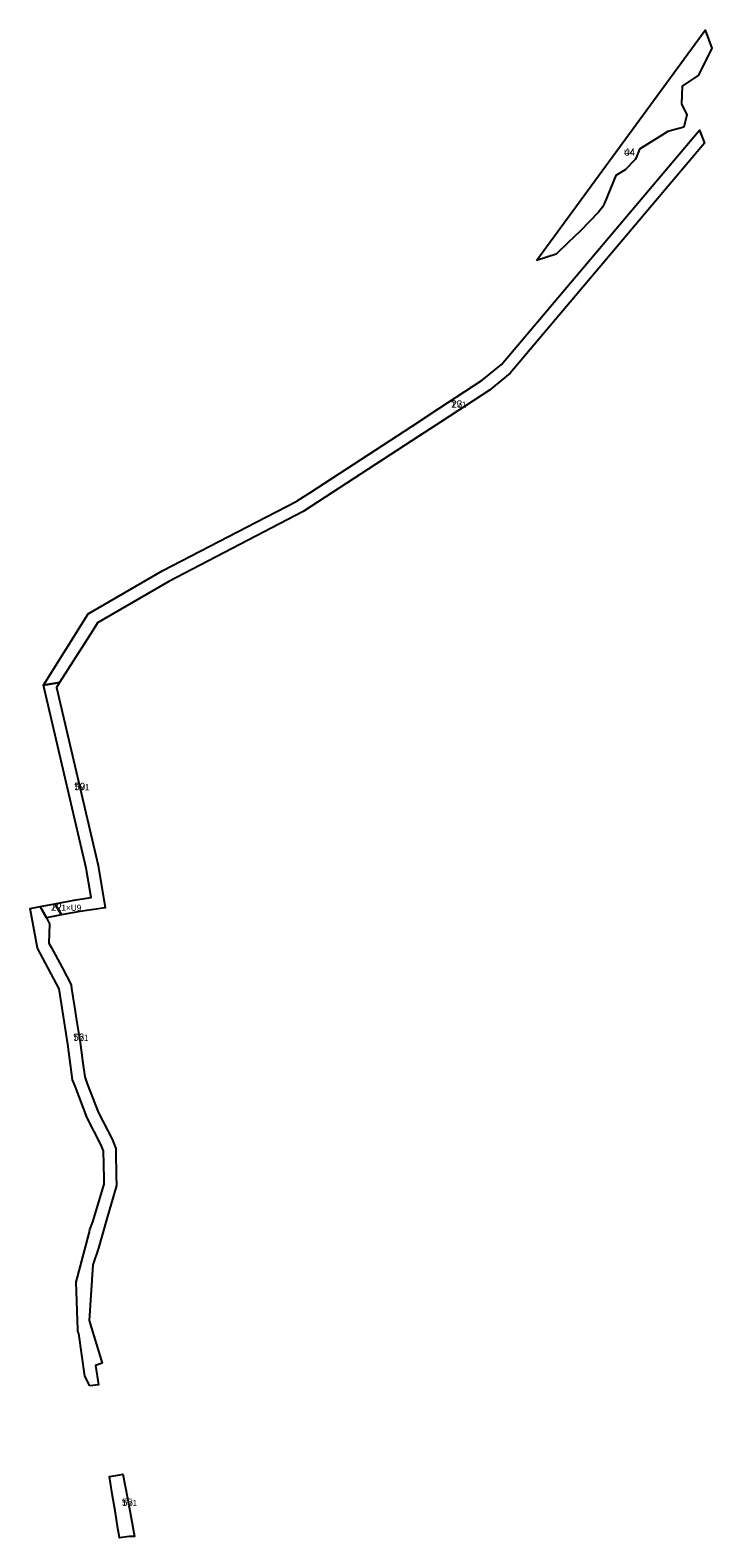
# Model space of a CAD drawing. Extents: x -521229 to -518220, y -1182332 to -1179899.
# Drawn here: x -519555 to -519000, y -1181125 to -1179899 of the extents above; entities that cross this region are included whole.
import ezdxf

# ---------------------------------------------------------------- set-up
doc = ezdxf.new("R2010")
doc.units = 0
for name, color, linetype in [('96120023', 7, 'Continuous'), ('96140023', 7, 'Continuous'), ('ID_VPO', 7, 'Continuous'), ('ID_VPS', 7, 'Continuous')]:
    doc.layers.add(name, color=color, linetype=linetype)

msp = doc.modelspace()

# ---------------------------------------------------------------- linework, layer by layer
at = {"layer": '96120023'}
for points in [[(-519543.8, -1180432.1), (-519507.4, -1180374), (-519446.6, -1180338.8), (-519370.8, -1180299.4), (-519337.8, -1180282.3), (-519337.7, -1180282.2), (-519337.5, -1180282.1), (-519327.1, -1180275.5), (-519244, -1180221.2), (-519222.2, -1180207), (-519187, -1180183.9), (-519171.3, -1180171.2), (-519012, -1179982.6), (-519010.3, -1179980.5), (-519006.1, -1179991.2), (-519164.2, -1180178.3), (-519181.1, -1180192), (-519220, -1180217.4), (-519238.6, -1180229.5), (-519332.5, -1180290.7), (-519441.8, -1180347.6), (-519499.7, -1180381.2), (-519503.7, -1180387.4), (-519530.6, -1180429.8)], [(-519543.8, -1180432.1), (-519530.6, -1180429.8), (-519533.1, -1180433.9), (-519499.2, -1180578.7), (-519493.5, -1180613), (-519515.7, -1180616.4), (-519529, -1180618.9), (-519534.4, -1180609.7), (-519517.4, -1180606.5), (-519505, -1180604.6), (-519509, -1180580.7)], [(-519505.9, -1181001.9), (-519510.2, -1180994.1), (-519515.1, -1180959.2), (-519515.9, -1180957.6), (-519515.9, -1180956.3), (-519517.2, -1180917.4), (-519506.7, -1180877.7), (-519505.9, -1180874.8), (-519503.5, -1180868.4), (-519494.4, -1180837.7), (-519494.5, -1180833.2), (-519495, -1180810.8), (-519497.1, -1180805.5), (-519508.2, -1180783.9), (-519518, -1180758.1), (-519520, -1180752.9), (-519523.9, -1180724), (-519530.9, -1180678.9), (-519548.5, -1180645.8), (-519554.6, -1180613.6), (-519546.3, -1180612), (-519541.3, -1180621.3), (-519538.7, -1180626), (-519539.3, -1180641.8), (-519537.6, -1180645), (-519528.5, -1180661.7), (-519521.3, -1180675.7), (-519520.9, -1180678.7), (-519518.6, -1180693.9), (-519516.6, -1180706.2), (-519514, -1180722.6), (-519511.6, -1180739.4), (-519510.2, -1180750.4), (-519508.1, -1180756.2), (-519499, -1180779.8), (-519488, -1180801.3), (-519485, -1180808.7), (-519485, -1180811.4), (-519484.6, -1180831.1), (-519484.4, -1180839), (-519492.5, -1180866.9), (-519498.9, -1180889.8), (-519503.7, -1180903.5), (-519506.5, -1180948.8), (-519495.9, -1180983.5), (-519495.9, -1180983.5), (-519501.3, -1180985.2), (-519499.1, -1181001), (-519505.9, -1181001.9)], [(-519534.4, -1180609.7), (-519529, -1180618.9), (-519541.3, -1180621.3), (-519546.3, -1180612)], [(-519483.4, -1181074.6), (-519482.9, -1181074.5), (-519481.7, -1181074.3), (-519479.1, -1181073.8), (-519475.5, -1181093.3), (-519472.8, -1181107.8), (-519469.7, -1181124.3), (-519472.4, -1181124.3), (-519474.1, -1181124.5), (-519482, -1181125.5), (-519482.2, -1181123.5), (-519483.2, -1181117.8), (-519485.2, -1181105.1), (-519488, -1181089.8), (-519489.3, -1181080.9), (-519490.1, -1181075.7), (-519486.8, -1181075.1), (-519485, -1181074.8)]]:
    msp.add_lwpolyline(points, close=True, dxfattribs=at)
at = {"layer": '96140023'}
for points in [[(-519142.9, -1180086.6), (-519005.7, -1179899.2), (-519000.3, -1179913.9), (-519011.1, -1179935.9), (-519024.4, -1179944.7), (-519024.9, -1179959.2), (-519020.6, -1179968), (-519023, -1179978), (-519036, -1179981.6), (-519059.1, -1179995.9), (-519061.8, -1180003.2), (-519062.7, -1180004.4), (-519070.6, -1180012.7), (-519078.4, -1180017.4), (-519087.6, -1180040), (-519089.2, -1180043.2), (-519092.5, -1180047.2), (-519107.3, -1180062.6), (-519117, -1180071.9), (-519126.8, -1180081.3)], [(-519534.4, -1180609.7), (-519529, -1180618.9), (-519541.3, -1180621.3), (-519546.3, -1180612), (-519546.3, -1180612)]]:
    msp.add_lwpolyline(points, close=True, dxfattribs=at)

# ---------------------------------------------------------------- texts
at = {"layer": '96120023'}
for s, rotation, p in [('TV1', 0, (-519212.1, -1180206.3)), ('TV1', 0, (-519518.7, -1180517.4)), ('TV1×U9', 360, (-519537.7, -1180615.5)), ('TV1', 0, (-519519.5, -1180721.3)), ('TV1', 360, (-519479.9, -1181099.6))]:
    msp.add_text(s, height=5, rotation=rotation, dxfattribs=at).set_placement(p)
at = {"layer": '96140023'}
for s, p in [('U4', (-519071.6, -1180001.3)), ('TV1×U9', (-519537.7, -1180615.5))]:
    msp.add_text(s, height=5, rotation=360, dxfattribs=at).set_placement(p)
at = {"layer": 'ID_VPO'}
for s, p in [('44', (-519071.6, -1180001.3)), ('22', (-519537.7, -1180615.5))]:
    msp.add_text(s, height=6, rotation=360, dxfattribs=at).set_placement(p)
at = {"layer": 'ID_VPS'}
for s, rotation, p in [('23', 0, (-519212.1, -1180206.3)), ('59', 360, (-519518.7, -1180517.4)), ('22', 360, (-519537.7, -1180615.5)), ('56', 0, (-519519.5, -1180721.3)), ('55', 360, (-519479.9, -1181099.6))]:
    msp.add_text(s, height=6, rotation=rotation, dxfattribs=at).set_placement(p)

doc.saveas('drawing.dxf')
